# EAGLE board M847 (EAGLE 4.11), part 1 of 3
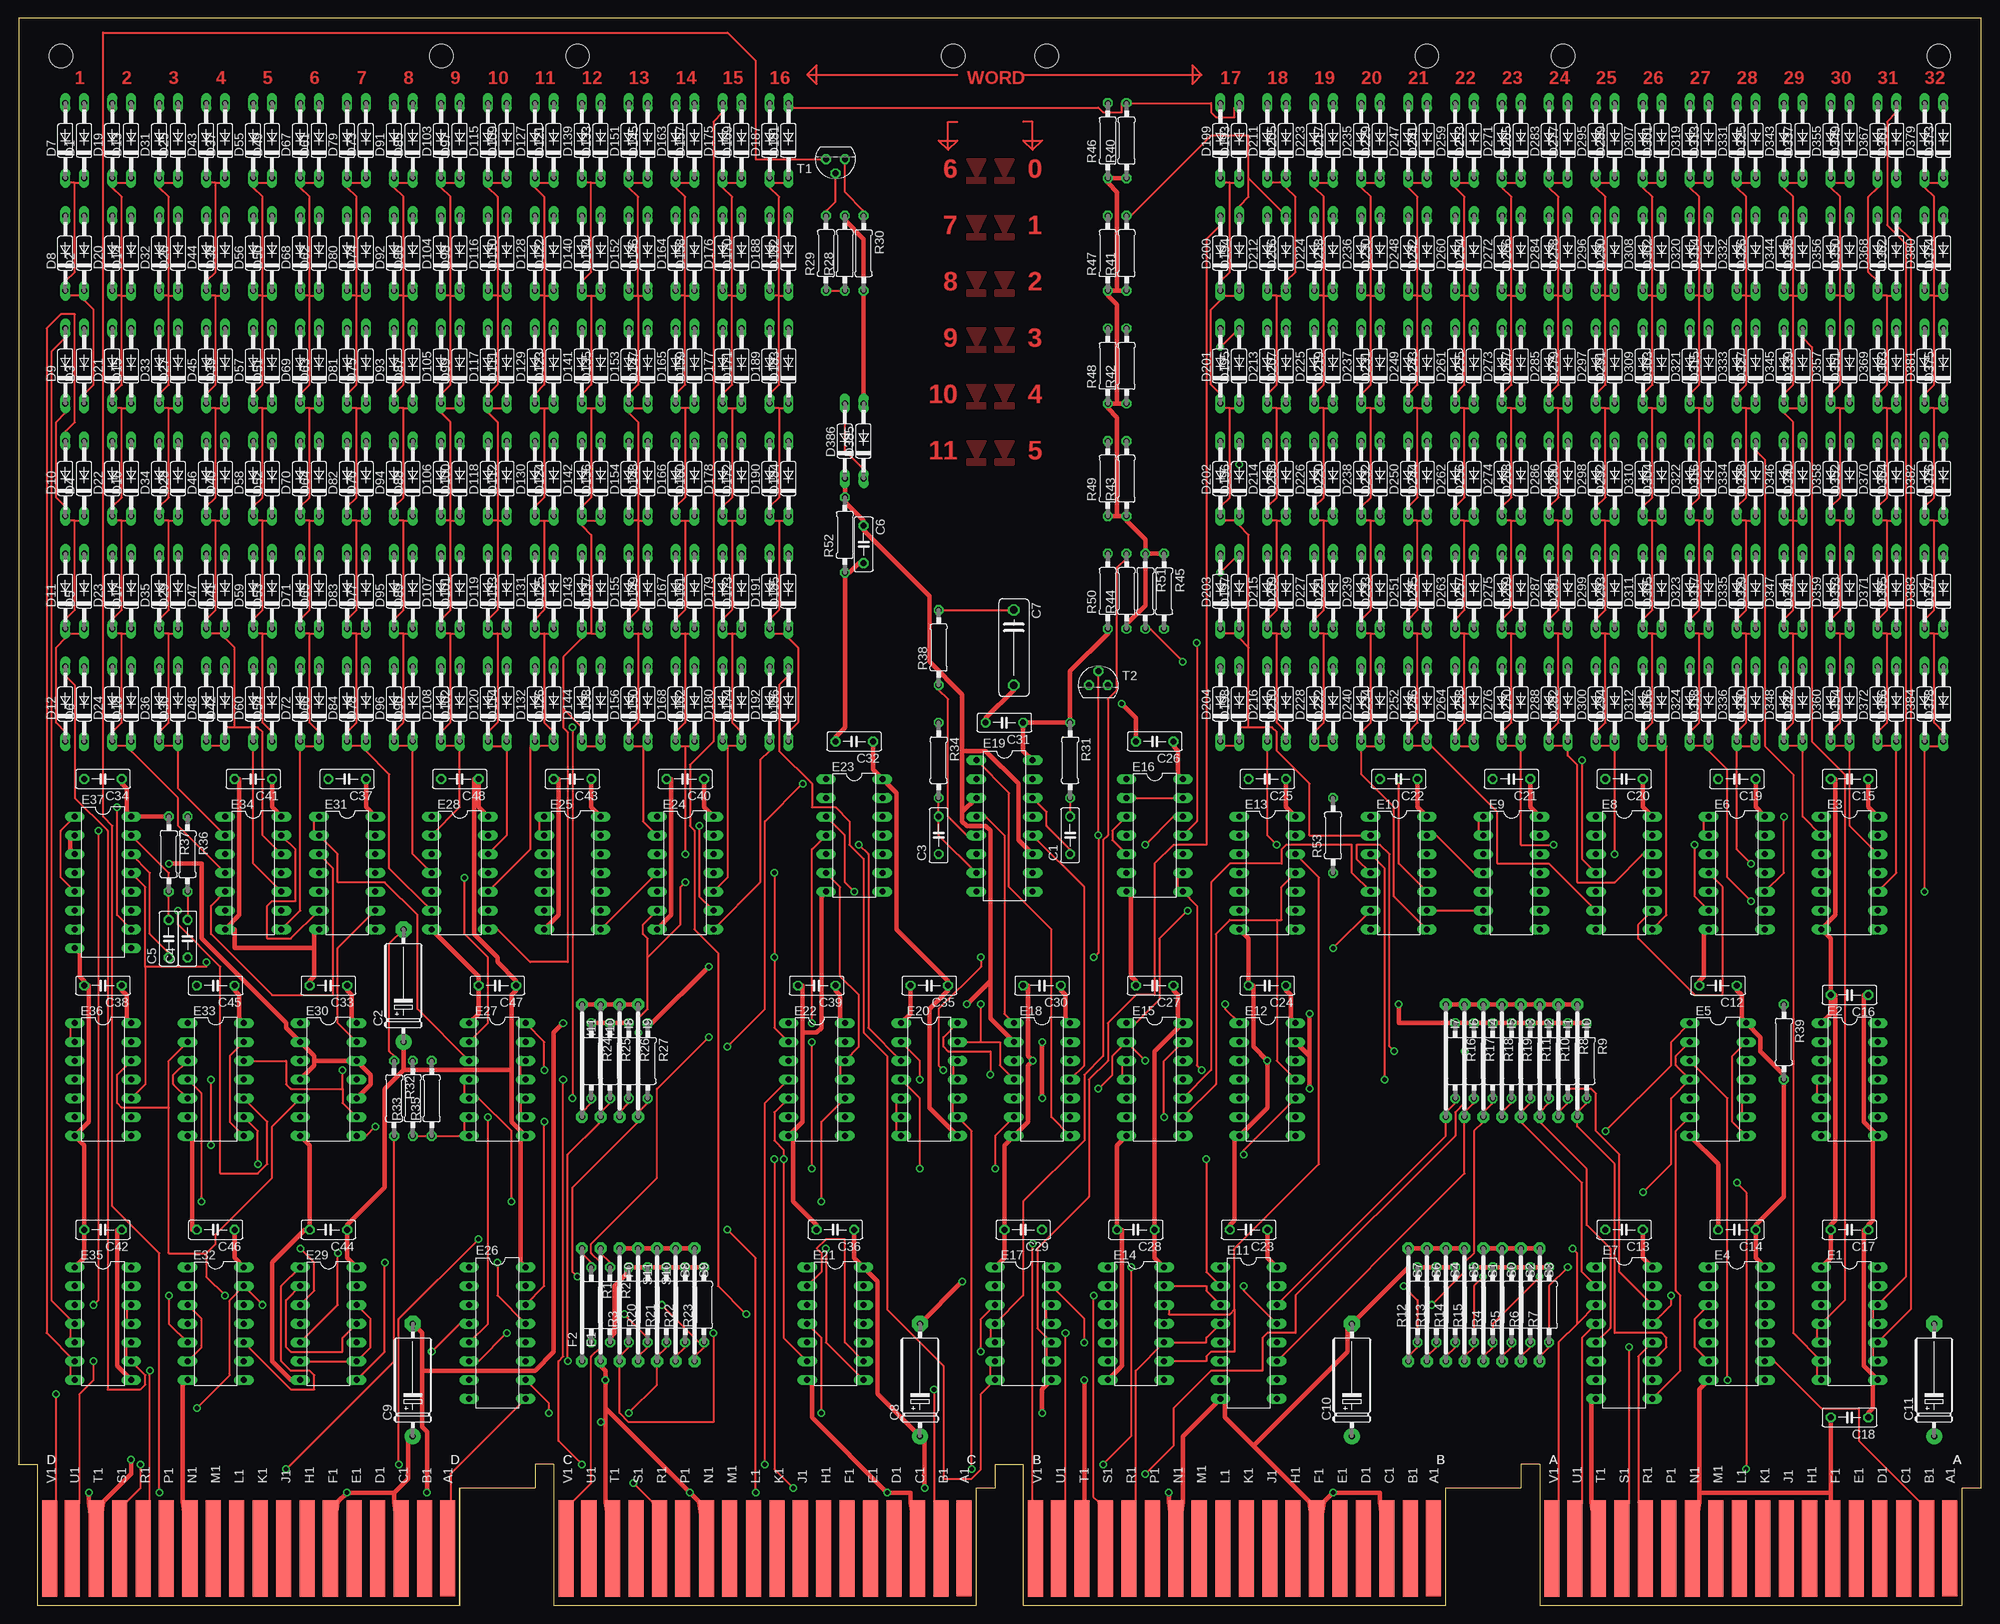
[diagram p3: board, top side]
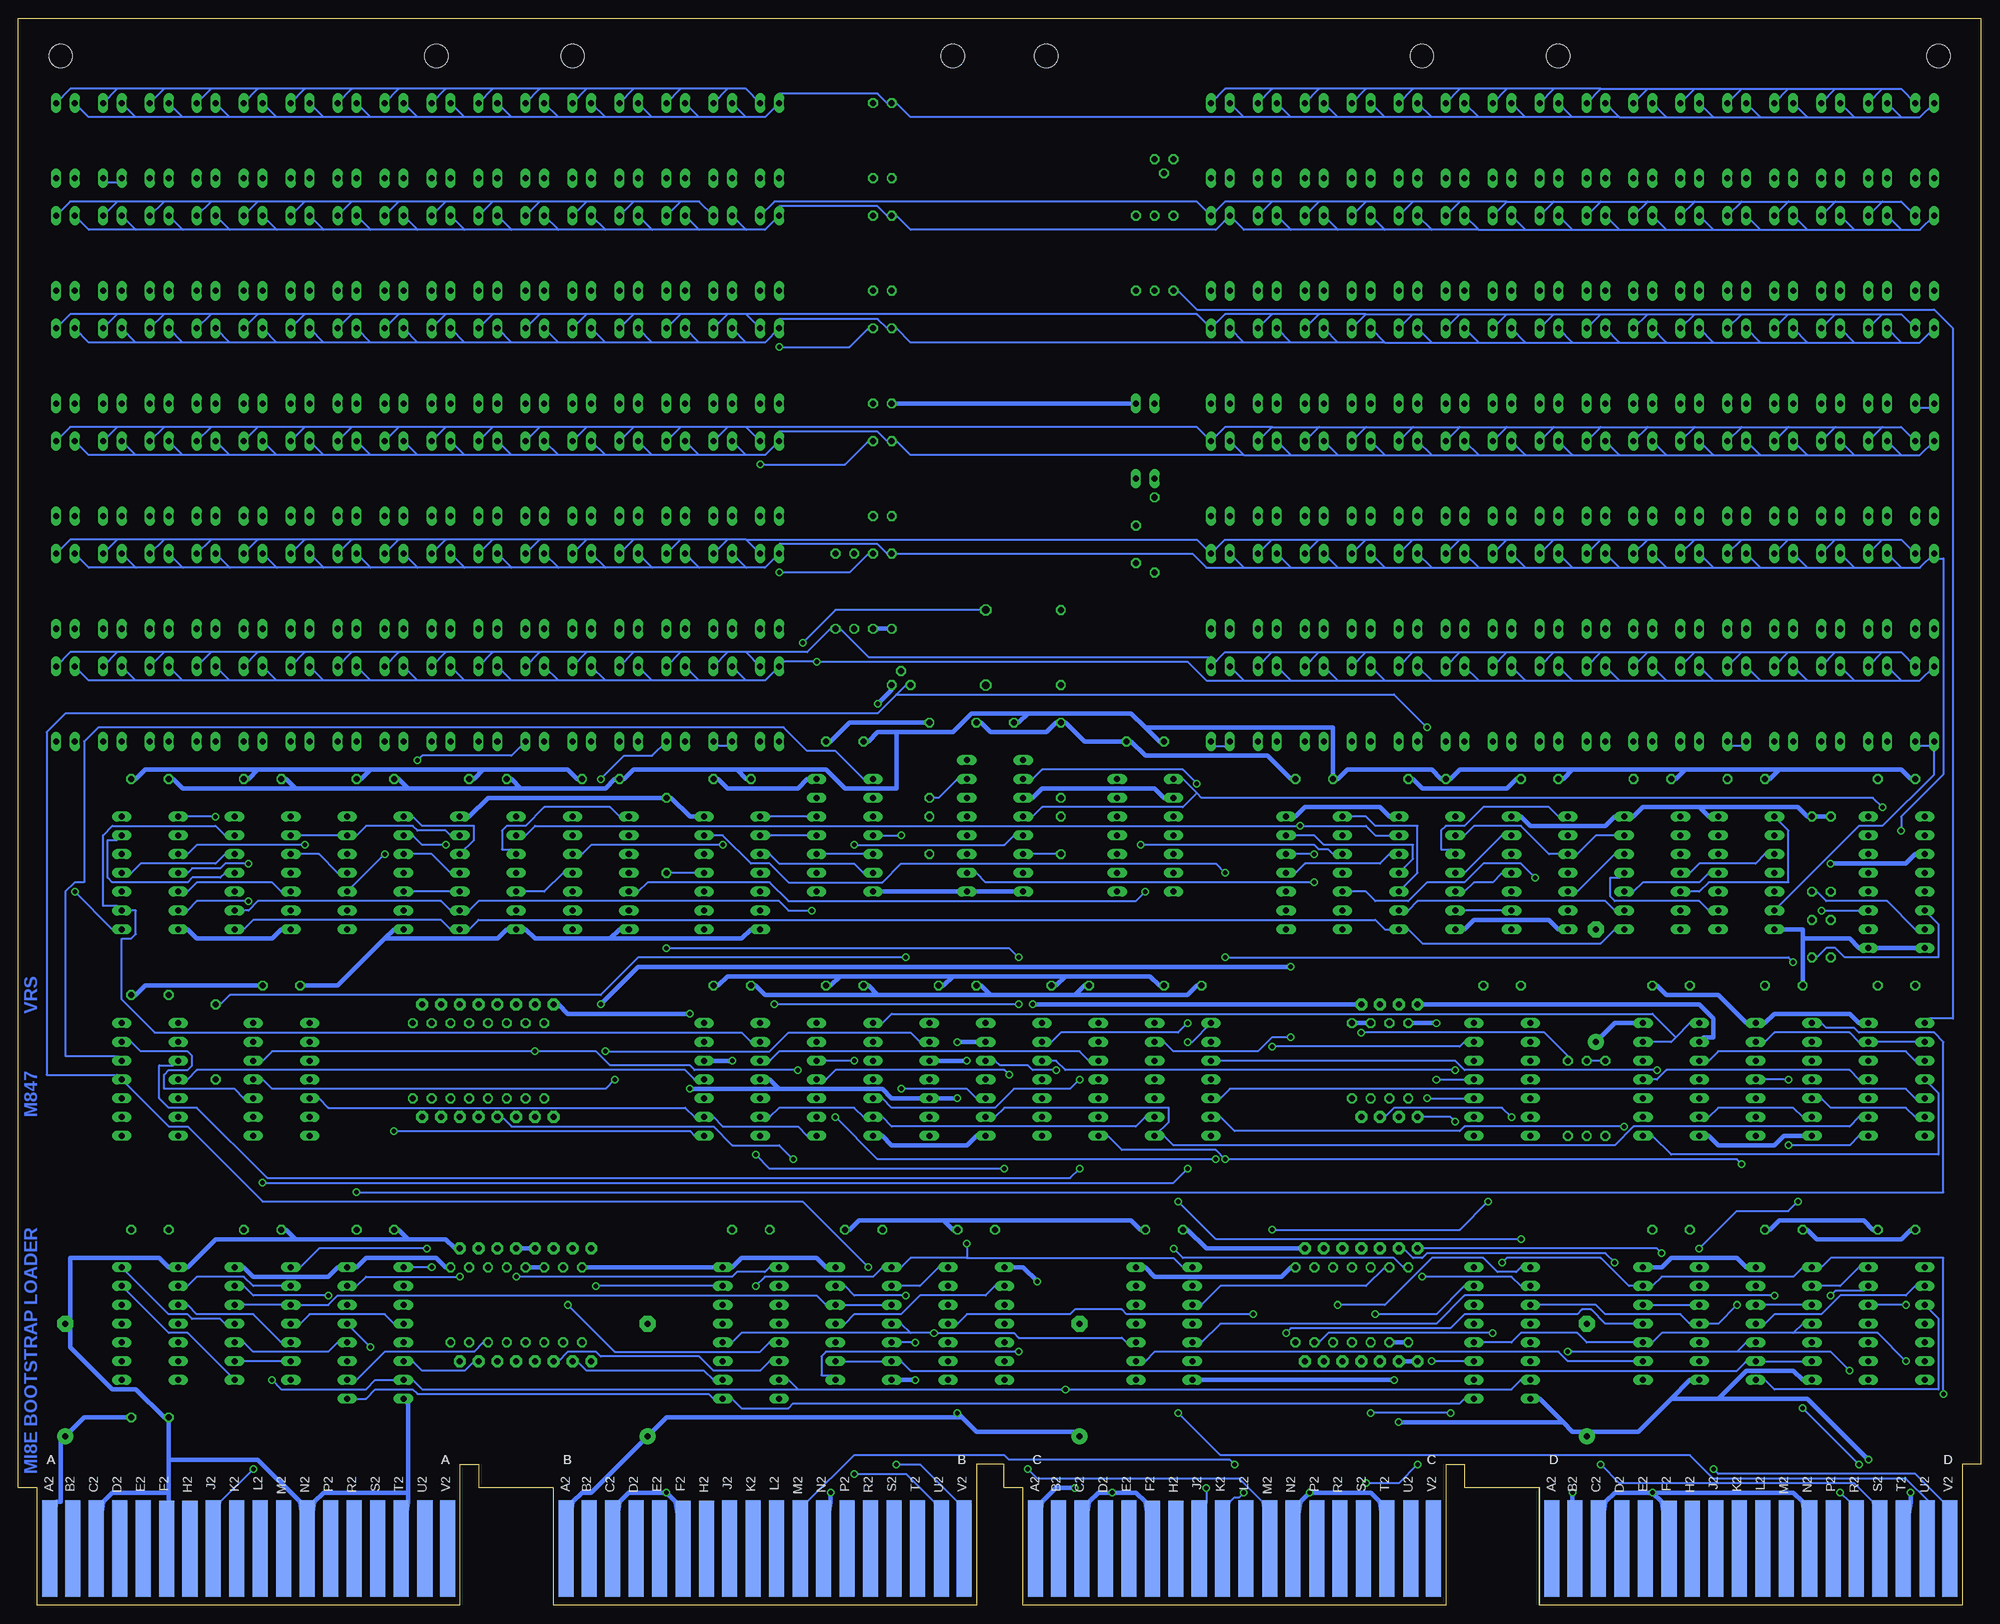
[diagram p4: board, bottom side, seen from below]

Size 265.43 x 214.63 mm. Coordinates in mm from the lower left corner, seen from the top.
Copper layers (1*16): Top 0.035mm / dielectric 1.5mm / Bottom 0.035mm
Design rules "10mils": minimum track width 10mil, minimum drill 24mil, track to track 10mil, track to pad 10mil, pad to pad 10mil, via to via 10mil, smd to smd 10mil, copper to edge 25mil, drill to drill 10mil, minimum pad ring 10mil, minimum via ring 8mil, stop-mask expansion 0mil, vias tented up to drill 0mil, thermal gap 10mil
Net classes: 1 supply: width 0.635 mm

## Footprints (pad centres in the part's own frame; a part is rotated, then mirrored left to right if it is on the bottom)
C050-025X075 = drill 0.813 octagon: 1 -2.54,0; 2 2.54,0
E15-5 = drill 0.813 pad 2.159 round: + -7.62,0 | drill 0.813 pad 2.159 octagon: - 7.62,0
C102-043X133 = drill 1.016 octagon: 1 -5.08,0; 2 5.08,0
DO35-10 = drill 0.813 long: A 5.08,0; C -5.08,0
DIL14 = drill 0.813 long: 1 -7.62,-3.81; 2 -5.08,-3.81; 3 -2.54,-3.81; 4 0,-3.81; 5 2.54,-3.81; 6 5.08,-3.81; 7 7.62,-3.81; 8 7.62,3.81; 9 5.08,3.81; 10 2.54,3.81; 11 0,3.81; 12 -2.54,3.81; 13 -5.08,3.81; 14 -7.62,3.81
DIL16 = drill 0.813 long: 1 -8.89,-3.81; 2 -6.35,-3.81; 3 -3.81,-3.81; 4 -1.27,-3.81; 5 1.27,-3.81; 6 3.81,-3.81; 7 6.35,-3.81; 8 8.89,-3.81; 9 8.89,3.81; 10 6.35,3.81; 11 3.81,3.81; 12 1.27,3.81; 13 -1.27,3.81; 14 -3.81,3.81; 15 -6.35,3.81; 16 -8.89,3.81
15 = drill 0.813 pad 1.6 octagon: 1 -7.62,0; 2 7.62,0
0207/10 = drill 0.813 octagon: 1 -5.08,0; 2 5.08,0
TO92 = drill 0.813 octagon: 1 1.27,0; 2 0,1.905; 3 -1.27,0
OMNIBUS = hole 3.175: 208.915,209.55; 259.715,209.55; 190.5,209.55; 139.065,209.55; 75.616,209.55; 126.416,209.55; 57.201,209.55; 5.766,209.55
EDGE-CON8 = smd 2.032 x 13.017: AA1 261.223,7.709; AB1 258.118,7.684; AC1 254.956,7.684; AD1 251.765,7.684; AE1 248.59,7.693; AF1 245.389,7.668; AH1 242.24,7.668; AJ1 239.09,7.668; AK1 235.915,7.668; AL1 232.74,7.693; AM1 229.54,7.693; AN1 226.39,7.693; AP1 223.19,7.668; AR1 220.04,7.668; AS1 216.865,7.693; AT1 213.69,7.693; AU1 210.49,7.693; AV1 207.404,7.668; BA1 191.373,7.709; BB1 188.268,7.684; BC1 185.106,7.684; BD1 181.915,7.684; BE1 178.74,7.693; BF1 175.539,7.668; BH1 172.39,7.668; BJ1 169.24,7.668; BK1 166.065,7.668; BL1 162.89,7.693; BM1 159.69,7.693; BN1 156.54,7.693; BP1 153.34,7.668; BR1 150.19,7.668; BS1 147.015,7.693; BT1 143.84,7.693; BU1 140.64,7.693; BV1 137.554,7.668; CA1 127.873,7.709; CB1 124.768,7.684; CC1 121.606,7.684; CD1 118.415,7.684; CE1 115.24,7.693; CF1 112.039,7.668; CH1 108.89,7.668; CJ1 105.74,7.668; CK1 102.565,7.668; CL1 99.39,7.693; CM1 96.19,7.693; CN1 93.04,7.693; CP1 89.84,7.668; CR1 86.69,7.668; CS1 83.515,7.693; CT1 80.34,7.693; CU1 77.14,7.693; CV1 74.054,7.668; DA1 58.023,7.709; DB1 54.918,7.684; DC1 51.756,7.684; DD1 48.565,7.684; DE1 45.39,7.693; DF1 42.189,7.668; DH1 39.04,7.668; DJ1 35.89,7.668; DK1 32.715,7.668; DL1 29.54,7.693; DM1 26.34,7.693; DN1 23.19,7.693; DP1 19.99,7.668; DR1 16.84,7.668; DS1 13.665,7.693; DT1 10.49,7.693; DU1 7.29,7.693; DV1 4.204,7.668 | smd 2.032 x 13.017 bottom: AA2 261.223,7.69; AB2 258.102,7.668; AC2 254.94,7.668; AD2 251.765,7.693; AE2 248.59,7.693; AF2 245.389,7.642; AH2 242.24,7.642; AJ2 239.09,7.668; AK2 235.915,7.668; AL2 232.74,7.693; AM2 229.54,7.693; AN2 226.39,7.693; AP2 223.19,7.668; AR2 220.04,7.668; AS2 216.865,7.693; AT2 213.69,7.693; AU2 210.464,7.693; AV2 207.404,7.668; BA2 191.373,7.69; BB2 188.252,7.668; BC2 185.09,7.668; BD2 181.915,7.693; BE2 178.74,7.693; BF2 175.539,7.642; BH2 172.39,7.642; BJ2 169.24,7.668; BK2 166.065,7.668; BL2 162.89,7.693; BM2 159.69,7.693; BN2 156.54,7.693; BP2 153.34,7.668; BR2 150.19,7.668; BS2 147.015,7.693; BT2 143.84,7.693; BU2 140.614,7.693; BV2 137.554,7.668; CA2 127.873,7.69; CB2 124.752,7.668; CC2 121.59,7.668; CD2 118.415,7.693; CE2 115.24,7.693; CF2 112.039,7.642; CH2 108.89,7.642; CJ2 105.74,7.668; CK2 102.565,7.668; CL2 99.39,7.693; CM2 96.19,7.693; CN2 93.04,7.693; CP2 89.84,7.668; CR2 86.69,7.668; CS2 83.515,7.693; CT2 80.34,7.693; CU2 77.114,7.693; CV2 74.054,7.668; DA2 58.023,7.69; DB2 54.902,7.668; DC2 51.74,7.668; DD2 48.565,7.693; DE2 45.39,7.693; DF2 42.189,7.642; DH2 39.04,7.642; DJ2 35.89,7.668; DK2 32.715,7.668; DL2 29.54,7.693; DM2 26.34,7.693; DN2 23.19,7.693; DP2 19.99,7.668; DR2 16.84,7.668; DS2 13.665,7.693; DT2 10.49,7.693; DU2 7.264,7.693; DV2 4.204,7.668

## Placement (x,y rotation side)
C1  27pf  [C050-025X075]  142.24,104.14 90 top
C2  39uf  [E15-5]  52.07,83.82 90 top
C3  150pf  [C050-025X075]  124.46,104.14 90 top
C4  68pf  [C050-025X075]  22.86,90.17 90 top
C5  27pf  [C050-025X075]  20.32,90.17 90 top
C6  27pf  [C050-025X075]  114.3,143.51 270 top
C7  2700pf  [C102-043X133]  134.62,129.54 270 top
C8  6.8uf  [E15-5]  121.92,30.48 90 top
C9  6.8uf  [E15-5]  53.34,30.48 90 top
C10  6.8uf  [E15-5]  180.34,30.48 90 top
C11  6.8uf  [E15-5]  259.08,30.48 90 top
C12  .01uf  [C050-025X075]  229.87,83.82 180 top
C13  .01uf  [C050-025X075]  217.17,50.8 180 top
C14  .01uf  [C050-025X075]  232.41,50.8 180 top
C15  .01uf  [C050-025X075]  247.65,111.76 180 top
C16  .01uf  [C050-025X075]  247.65,82.55 180 top
C17  .01uf  [C050-025X075]  247.65,50.8 180 top
C18  .01uf  [C050-025X075]  247.65,25.4 180 top
C19  .01uf  [C050-025X075]  232.41,111.76 180 top
C20  .01uf  [C050-025X075]  217.17,111.76 180 top
C21  .01uf  [C050-025X075]  201.93,111.76 180 top
C22  .01uf  [C050-025X075]  186.69,111.76 180 top
C23  .01uf  [C050-025X075]  166.37,50.8 180 top
C24  .01uf  [C050-025X075]  168.91,83.82 180 top
C25  .01uf  [C050-025X075]  168.91,111.76 180 top
C26  .01uf  [C050-025X075]  153.67,116.84 180 top
C27  .01uf  [C050-025X075]  153.67,83.82 180 top
C28  .01uf  [C050-025X075]  151.13,50.8 180 top
C29  .01uf  [C050-025X075]  135.89,50.8 180 top
C30  .01uf  [C050-025X075]  138.43,83.82 180 top
C31  .01uf  [C050-025X075]  133.35,119.38 180 top
C32  .01uf  [C050-025X075]  113.03,116.84 180 top
C33  .01uf  [C050-025X075]  41.91,83.82 180 top
C34  .01uf  [C050-025X075]  11.43,111.76 180 top
C35  .01uf  [C050-025X075]  123.19,83.82 180 top
C36  .01uf  [C050-025X075]  110.49,50.8 180 top
C37  .01uf  [C050-025X075]  44.45,111.76 180 top
C38  .01uf  [C050-025X075]  11.43,83.82 180 top
C39  .01uf  [C050-025X075]  107.95,83.82 180 top
C40  .01uf  [C050-025X075]  90.17,111.76 180 top
C41  .01uf  [C050-025X075]  31.75,111.76 180 top
C42  .01uf  [C050-025X075]  11.43,50.8 180 top
C43  .01uf  [C050-025X075]  74.93,111.76 180 top
C44  .01uf  [C050-025X075]  41.91,50.8 180 top
C45  .01uf  [C050-025X075]  26.67,83.82 180 top
C46  .01uf  [C050-025X075]  26.67,50.8 180 top
C47  .01uf  [C050-025X075]  64.77,83.82 180 top
C48  .01uf  [C050-025X075]  59.69,111.76 180 top
D1  1N4148  [DO35-10]  8.89,198.12 90 top
D2  1N4148  [DO35-10]  8.89,182.88 90 top
D3  1N4148  [DO35-10]  8.89,167.64 90 top
D4  1N4148  [DO35-10]  8.89,152.4 90 top
D5  1N4148  [DO35-10]  8.89,137.16 90 top
D6  1N4148  [DO35-10]  8.89,121.92 90 top
D7  1N4148  [DO35-10]  6.35,198.12 90 top
D8  1N4148  [DO35-10]  6.35,182.88 90 top
D9  1N4148  [DO35-10]  6.35,167.64 90 top
D10  1N4148  [DO35-10]  6.35,152.4 90 top
D11  1N4148  [DO35-10]  6.35,137.16 90 top
D12  1N4148  [DO35-10]  6.35,121.92 90 top
D13  1N4148  [DO35-10]  15.24,198.12 90 top
D14  1N4148  [DO35-10]  15.24,182.88 90 top
D15  1N4148  [DO35-10]  15.24,167.64 90 top
D16  1N4148  [DO35-10]  15.24,152.4 90 top
D17  1N4148  [DO35-10]  15.24,137.16 90 top
D18  1N4148  [DO35-10]  15.24,121.92 90 top
D19  1N4148  [DO35-10]  12.7,198.12 90 top
D20  1N4148  [DO35-10]  12.7,182.88 90 top
D21  1N4148  [DO35-10]  12.7,167.64 90 top
D22  1N4148  [DO35-10]  12.7,152.4 90 top
D23  1N4148  [DO35-10]  12.7,137.16 90 top
D24  1N4148  [DO35-10]  12.7,121.92 90 top
D25  1N4148  [DO35-10]  21.59,198.12 90 top
D26  1N4148  [DO35-10]  21.59,182.88 90 top
D27  1N4148  [DO35-10]  21.59,167.64 90 top
D28  1N4148  [DO35-10]  21.59,152.4 90 top
D29  1N4148  [DO35-10]  21.59,137.16 90 top
D30  1N4148  [DO35-10]  21.59,121.92 90 top
D31  1N4148  [DO35-10]  19.05,198.12 90 top
D32  1N4148  [DO35-10]  19.05,182.88 90 top
D33  1N4148  [DO35-10]  19.05,167.64 90 top
D34  1N4148  [DO35-10]  19.05,152.4 90 top
D35  1N4148  [DO35-10]  19.05,137.16 90 top
D36  1N4148  [DO35-10]  19.05,121.92 90 top
D37  1N4148  [DO35-10]  27.94,198.12 90 top
D38  1N4148  [DO35-10]  27.94,182.88 90 top
D39  1N4148  [DO35-10]  27.94,167.64 90 top
D40  1N4148  [DO35-10]  27.94,152.4 90 top
D41  1N4148  [DO35-10]  27.94,137.16 90 top
D42  1N4148  [DO35-10]  27.94,121.92 90 top
D43  1N4148  [DO35-10]  25.4,198.12 90 top
D44  1N4148  [DO35-10]  25.4,182.88 90 top
D45  1N4148  [DO35-10]  25.4,167.64 90 top
D46  1N4148  [DO35-10]  25.4,152.4 90 top
D47  1N4148  [DO35-10]  25.4,137.16 90 top
D48  1N4148  [DO35-10]  25.4,121.92 90 top
D49  1N4148  [DO35-10]  34.29,198.12 90 top
D50  1N4148  [DO35-10]  34.29,182.88 90 top
D51  1N4148  [DO35-10]  34.29,167.64 90 top
D52  1N4148  [DO35-10]  34.29,152.4 90 top
D53  1N4148  [DO35-10]  34.29,137.16 90 top
D54  1N4148  [DO35-10]  34.29,121.92 90 top
D55  1N4148  [DO35-10]  31.75,198.12 90 top
D56  1N4148  [DO35-10]  31.75,182.88 90 top
D57  1N4148  [DO35-10]  31.75,167.64 90 top
D58  1N4148  [DO35-10]  31.75,152.4 90 top
D59  1N4148  [DO35-10]  31.75,137.16 90 top
D60  1N4148  [DO35-10]  31.75,121.92 90 top
D61  1N4148  [DO35-10]  40.64,198.12 90 top
D62  1N4148  [DO35-10]  40.64,182.88 90 top
D63  1N4148  [DO35-10]  40.64,167.64 90 top
D64  1N4148  [DO35-10]  40.64,152.4 90 top
D65  1N4148  [DO35-10]  40.64,137.16 90 top
D66  1N4148  [DO35-10]  40.64,121.92 90 top
D67  1N4148  [DO35-10]  38.1,198.12 90 top
D68  1N4148  [DO35-10]  38.1,182.88 90 top
D69  1N4148  [DO35-10]  38.1,167.64 90 top
D70  1N4148  [DO35-10]  38.1,152.4 90 top
D71  1N4148  [DO35-10]  38.1,137.16 90 top
D72  1N4148  [DO35-10]  38.1,121.92 90 top
D73  1N4148  [DO35-10]  46.99,198.12 90 top
D74  1N4148  [DO35-10]  46.99,182.88 90 top
D75  1N4148  [DO35-10]  46.99,167.64 90 top
D76  1N4148  [DO35-10]  46.99,152.4 90 top
D77  1N4148  [DO35-10]  46.99,137.16 90 top
D78  1N4148  [DO35-10]  46.99,121.92 90 top
D79  1N4148  [DO35-10]  44.45,198.12 90 top
D80  1N4148  [DO35-10]  44.45,182.88 90 top
D81  1N4148  [DO35-10]  44.45,167.64 90 top
D82  1N4148  [DO35-10]  44.45,152.4 90 top
D83  1N4148  [DO35-10]  44.45,137.16 90 top
D84  1N4148  [DO35-10]  44.45,121.92 90 top
D85  1N4148  [DO35-10]  53.34,198.12 90 top
D86  1N4148  [DO35-10]  53.34,182.88 90 top
D87  1N4148  [DO35-10]  53.34,167.64 90 top
D88  1N4148  [DO35-10]  53.34,152.4 90 top
D89  1N4148  [DO35-10]  53.34,137.16 90 top
D90  1N4148  [DO35-10]  53.34,121.92 90 top
D91  1N4148  [DO35-10]  50.8,198.12 90 top
D92  1N4148  [DO35-10]  50.8,182.88 90 top
D93  1N4148  [DO35-10]  50.8,167.64 90 top
D94  1N4148  [DO35-10]  50.8,152.4 90 top
D95  1N4148  [DO35-10]  50.8,137.16 90 top
D96  1N4148  [DO35-10]  50.8,121.92 90 top
D97  1N4148  [DO35-10]  59.69,198.12 90 top
D98  1N4148  [DO35-10]  59.69,182.88 90 top
D99  1N4148  [DO35-10]  59.69,167.64 90 top
D100  1N4148  [DO35-10]  59.69,152.4 90 top
D101  1N4148  [DO35-10]  59.69,137.16 90 top
D102  1N4148  [DO35-10]  59.69,121.92 90 top
D103  1N4148  [DO35-10]  57.15,198.12 90 top
D104  1N4148  [DO35-10]  57.15,182.88 90 top
D105  1N4148  [DO35-10]  57.15,167.64 90 top
D106  1N4148  [DO35-10]  57.15,152.4 90 top
D107  1N4148  [DO35-10]  57.15,137.16 90 top
D108  1N4148  [DO35-10]  57.15,121.92 90 top
D109  1N4148  [DO35-10]  66.04,198.12 90 top
D110  1N4148  [DO35-10]  66.04,182.88 90 top
D111  1N4148  [DO35-10]  66.04,167.64 90 top
D112  1N4148  [DO35-10]  66.04,152.4 90 top
D113  1N4148  [DO35-10]  66.04,137.16 90 top
D114  1N4148  [DO35-10]  66.04,121.92 90 top
D115  1N4148  [DO35-10]  63.5,198.12 90 top
D116  1N4148  [DO35-10]  63.5,182.88 90 top
D117  1N4148  [DO35-10]  63.5,167.64 90 top
D118  1N4148  [DO35-10]  63.5,152.4 90 top
D119  1N4148  [DO35-10]  63.5,137.16 90 top
D120  1N4148  [DO35-10]  63.5,121.92 90 top
D121  1N4148  [DO35-10]  72.39,198.12 90 top
D122  1N4148  [DO35-10]  72.39,182.88 90 top
D123  1N4148  [DO35-10]  72.39,167.64 90 top
D124  1N4148  [DO35-10]  72.39,152.4 90 top
D125  1N4148  [DO35-10]  72.39,137.16 90 top
D126  1N4148  [DO35-10]  72.39,121.92 90 top
D127  1N4148  [DO35-10]  69.85,198.12 90 top
D128  1N4148  [DO35-10]  69.85,182.88 90 top
D129  1N4148  [DO35-10]  69.85,167.64 90 top
D130  1N4148  [DO35-10]  69.85,152.4 90 top
D131  1N4148  [DO35-10]  69.85,137.16 90 top
D132  1N4148  [DO35-10]  69.85,121.92 90 top
D133  1N4148  [DO35-10]  78.74,198.12 90 top
D134  1N4148  [DO35-10]  78.74,182.88 90 top
D135  1N4148  [DO35-10]  78.74,167.64 90 top
D136  1N4148  [DO35-10]  78.74,152.4 90 top
D137  1N4148  [DO35-10]  78.74,137.16 90 top
D138  1N4148  [DO35-10]  78.74,121.92 90 top
D139  1N4148  [DO35-10]  76.2,198.12 90 top
D140  1N4148  [DO35-10]  76.2,182.88 90 top
D141  1N4148  [DO35-10]  76.2,167.64 90 top
D142  1N4148  [DO35-10]  76.2,152.4 90 top
D143  1N4148  [DO35-10]  76.2,137.16 90 top
D144  1N4148  [DO35-10]  76.2,121.92 90 top
D145  1N4148  [DO35-10]  85.09,198.12 90 top
D146  1N4148  [DO35-10]  85.09,182.88 90 top
D147  1N4148  [DO35-10]  85.09,167.64 90 top
D148  1N4148  [DO35-10]  85.09,152.4 90 top
D149  1N4148  [DO35-10]  85.09,137.16 90 top
D150  1N4148  [DO35-10]  85.09,121.92 90 top
D151  1N4148  [DO35-10]  82.55,198.12 90 top
D152  1N4148  [DO35-10]  82.55,182.88 90 top
D153  1N4148  [DO35-10]  82.55,167.64 90 top
D154  1N4148  [DO35-10]  82.55,152.4 90 top
D155  1N4148  [DO35-10]  82.55,137.16 90 top
D156  1N4148  [DO35-10]  82.55,121.92 90 top
D157  1N4148  [DO35-10]  91.44,198.12 90 top
D158  1N4148  [DO35-10]  91.44,182.88 90 top
D159  1N4148  [DO35-10]  91.44,167.64 90 top
D160  1N4148  [DO35-10]  91.44,152.4 90 top
D161  1N4148  [DO35-10]  91.44,137.16 90 top
D162  1N4148  [DO35-10]  91.44,121.92 90 top
D163  1N4148  [DO35-10]  88.9,198.12 90 top
D164  1N4148  [DO35-10]  88.9,182.88 90 top
D165  1N4148  [DO35-10]  88.9,167.64 90 top
D166  1N4148  [DO35-10]  88.9,152.4 90 top
D167  1N4148  [DO35-10]  88.9,137.16 90 top
D168  1N4148  [DO35-10]  88.9,121.92 90 top
D169  1N4148  [DO35-10]  97.79,198.12 90 top
D170  1N4148  [DO35-10]  97.79,182.88 90 top
D171  1N4148  [DO35-10]  97.79,167.64 90 top
D172  1N4148  [DO35-10]  97.79,152.4 90 top
D173  1N4148  [DO35-10]  97.79,137.16 90 top
D174  1N4148  [DO35-10]  97.79,121.92 90 top
D175  1N4148  [DO35-10]  95.25,198.12 90 top
D176  1N4148  [DO35-10]  95.25,182.88 90 top
D177  1N4148  [DO35-10]  95.25,167.64 90 top
D178  1N4148  [DO35-10]  95.25,152.4 90 top
D179  1N4148  [DO35-10]  95.25,137.16 90 top
D180  1N4148  [DO35-10]  95.25,121.92 90 top
D181  1N4148  [DO35-10]  104.14,198.12 90 top
D182  1N4148  [DO35-10]  104.14,182.88 90 top
D183  1N4148  [DO35-10]  104.14,167.64 90 top
D184  1N4148  [DO35-10]  104.14,152.4 90 top
D185  1N4148  [DO35-10]  104.14,137.16 90 top
D186  1N4148  [DO35-10]  104.14,121.92 90 top
D187  1N4148  [DO35-10]  101.6,198.12 90 top
D188  1N4148  [DO35-10]  101.6,182.88 90 top
D189  1N4148  [DO35-10]  101.6,167.64 90 top
D190  1N4148  [DO35-10]  101.6,152.4 90 top
D191  1N4148  [DO35-10]  101.6,137.16 90 top
D192  1N4148  [DO35-10]  101.6,121.92 90 top
D193  1N4148  [DO35-10]  165.1,198.12 90 top
D194  1N4148  [DO35-10]  165.1,182.88 90 top
D195  1N4148  [DO35-10]  165.1,167.64 90 top
D196  1N4148  [DO35-10]  165.1,152.4 90 top
D197  1N4148  [DO35-10]  165.1,137.16 90 top
D198  1N4148  [DO35-10]  165.1,121.92 90 top
D199  1N4148  [DO35-10]  162.56,198.12 90 top
D200  1N4148  [DO35-10]  162.56,182.88 90 top
D201  1N4148  [DO35-10]  162.56,167.64 90 top
D202  1N4148  [DO35-10]  162.56,152.4 90 top
D203  1N4148  [DO35-10]  162.56,137.16 90 top
D204  1N4148  [DO35-10]  162.56,121.92 90 top
D205  1N4148  [DO35-10]  171.45,198.12 90 top
D206  1N4148  [DO35-10]  171.45,182.88 90 top
D207  1N4148  [DO35-10]  171.45,167.64 90 top
D208  1N4148  [DO35-10]  171.45,152.4 90 top
D209  1N4148  [DO35-10]  171.45,137.16 90 top
D210  1N4148  [DO35-10]  171.45,121.92 90 top
D211  1N4148  [DO35-10]  168.91,198.12 90 top
D212  1N4148  [DO35-10]  168.91,182.88 90 top
D213  1N4148  [DO35-10]  168.91,167.64 90 top
D214  1N4148  [DO35-10]  168.91,152.4 90 top
D215  1N4148  [DO35-10]  168.91,137.16 90 top
D216  1N4148  [DO35-10]  168.91,121.92 90 top
D217  1N4148  [DO35-10]  177.8,198.12 90 top
D218  1N4148  [DO35-10]  177.8,182.88 90 top
D219  1N4148  [DO35-10]  177.8,167.64 90 top
D220  1N4148  [DO35-10]  177.8,152.4 90 top
D221  1N4148  [DO35-10]  177.8,137.16 90 top
D222  1N4148  [DO35-10]  177.8,121.92 90 top
D223  1N4148  [DO35-10]  175.26,198.12 90 top
D224  1N4148  [DO35-10]  175.26,182.88 90 top
D225  1N4148  [DO35-10]  175.26,167.64 90 top
D226  1N4148  [DO35-10]  175.26,152.4 90 top
D227  1N4148  [DO35-10]  175.26,137.16 90 top
D228  1N4148  [DO35-10]  175.26,121.92 90 top
D229  1N4148  [DO35-10]  184.15,198.12 90 top
D230  1N4148  [DO35-10]  184.15,182.88 90 top
D231  1N4148  [DO35-10]  184.15,167.64 90 top
D232  1N4148  [DO35-10]  184.15,152.4 90 top
D233  1N4148  [DO35-10]  184.15,137.16 90 top
D234  1N4148  [DO35-10]  184.15,121.92 90 top
D235  1N4148  [DO35-10]  181.61,198.12 90 top
D236  1N4148  [DO35-10]  181.61,182.88 90 top
D237  1N4148  [DO35-10]  181.61,167.64 90 top
D238  1N4148  [DO35-10]  181.61,152.4 90 top
D239  1N4148  [DO35-10]  181.61,137.16 90 top
D240  1N4148  [DO35-10]  181.61,121.92 90 top
D241  1N4148  [DO35-10]  190.5,198.12 90 top
D242  1N4148  [DO35-10]  190.5,182.88 90 top
D243  1N4148  [DO35-10]  190.5,167.64 90 top
D244  1N4148  [DO35-10]  190.5,152.4 90 top
D245  1N4148  [DO35-10]  190.5,137.16 90 top
D246  1N4148  [DO35-10]  190.5,121.92 90 top
D247  1N4148  [DO35-10]  187.96,198.12 90 top
D248  1N4148  [DO35-10]  187.96,182.88 90 top
D249  1N4148  [DO35-10]  187.96,167.64 90 top
D250  1N4148  [DO35-10]  187.96,152.4 90 top
D251  1N4148  [DO35-10]  187.96,137.16 90 top
D252  1N4148  [DO35-10]  187.96,121.92 90 top
D253  1N4148  [DO35-10]  196.85,198.12 90 top
D254  1N4148  [DO35-10]  196.85,182.88 90 top
D255  1N4148  [DO35-10]  196.85,167.64 90 top
D256  1N4148  [DO35-10]  196.85,152.4 90 top
D257  1N4148  [DO35-10]  196.85,137.16 90 top
D258  1N4148  [DO35-10]  196.85,121.92 90 top
D259  1N4148  [DO35-10]  194.31,198.12 90 top
D260  1N4148  [DO35-10]  194.31,182.88 90 top
D261  1N4148  [DO35-10]  194.31,167.64 90 top
D262  1N4148  [DO35-10]  194.31,152.4 90 top
D263  1N4148  [DO35-10]  194.31,137.16 90 top
D264  1N4148  [DO35-10]  194.31,121.92 90 top
D265  1N4148  [DO35-10]  203.2,198.12 90 top
D266  1N4148  [DO35-10]  203.2,182.88 90 top
D267  1N4148  [DO35-10]  203.2,167.64 90 top
D268  1N4148  [DO35-10]  203.2,152.4 90 top
D269  1N4148  [DO35-10]  203.2,137.16 90 top
D270  1N4148  [DO35-10]  203.2,121.92 90 top
D271  1N4148  [DO35-10]  200.66,198.12 90 top
D272  1N4148  [DO35-10]  200.66,182.88 90 top
D273  1N4148  [DO35-10]  200.66,167.64 90 top
D274  1N4148  [DO35-10]  200.66,152.4 90 top
D275  1N4148  [DO35-10]  200.66,137.16 90 top
D276  1N4148  [DO35-10]  200.66,121.92 90 top
D277  1N4148  [DO35-10]  209.55,198.12 90 top
D278  1N4148  [DO35-10]  209.55,182.88 90 top
D279  1N4148  [DO35-10]  209.55,167.64 90 top
D280  1N4148  [DO35-10]  209.55,152.4 90 top
D281  1N4148  [DO35-10]  209.55,137.16 90 top
D282  1N4148  [DO35-10]  209.55,121.92 90 top
D283  1N4148  [DO35-10]  207.01,198.12 90 top
D284  1N4148  [DO35-10]  207.01,182.88 90 top
D285  1N4148  [DO35-10]  207.01,167.64 90 top
D286  1N4148  [DO35-10]  207.01,152.4 90 top
D287  1N4148  [DO35-10]  207.01,137.16 90 top
D288  1N4148  [DO35-10]  207.01,121.92 90 top
D289  1N4148  [DO35-10]  215.9,198.12 90 top
D290  1N4148  [DO35-10]  215.9,182.88 90 top
D291  1N4148  [DO35-10]  215.9,167.64 90 top
D292  1N4148  [DO35-10]  215.9,152.4 90 top
D293  1N4148  [DO35-10]  215.9,137.16 90 top
D294  1N4148  [DO35-10]  215.9,121.92 90 top
D295  1N4148  [DO35-10]  213.36,198.12 90 top
D296  1N4148  [DO35-10]  213.36,182.88 90 top
D297  1N4148  [DO35-10]  213.36,167.64 90 top
D298  1N4148  [DO35-10]  213.36,152.4 90 top
D299  1N4148  [DO35-10]  213.36,137.16 90 top
D300  1N4148  [DO35-10]  213.36,121.92 90 top
D301  1N4148  [DO35-10]  222.25,198.12 90 top
D302  1N4148  [DO35-10]  222.25,182.88 90 top
D303  1N4148  [DO35-10]  222.25,167.64 90 top
D304  1N4148  [DO35-10]  222.25,152.4 90 top
D305  1N4148  [DO35-10]  222.25,137.16 90 top
D306  1N4148  [DO35-10]  222.25,121.92 90 top
D307  1N4148  [DO35-10]  219.71,198.12 90 top
D308  1N4148  [DO35-10]  219.71,182.88 90 top
D309  1N4148  [DO35-10]  219.71,167.64 90 top
D310  1N4148  [DO35-10]  219.71,152.4 90 top
D311  1N4148  [DO35-10]  219.71,137.16 90 top
D312  1N4148  [DO35-10]  219.71,121.92 90 top
D313  1N4148  [DO35-10]  228.6,198.12 90 top
D314  1N4148  [DO35-10]  228.6,182.88 90 top
D315  1N4148  [DO35-10]  228.6,167.64 90 top
D316  1N4148  [DO35-10]  228.6,152.4 90 top
D317  1N4148  [DO35-10]  228.6,137.16 90 top
D318  1N4148  [DO35-10]  228.6,121.92 90 top
D319  1N4148  [DO35-10]  226.06,198.12 90 top
D320  1N4148  [DO35-10]  226.06,182.88 90 top
D321  1N4148  [DO35-10]  226.06,167.64 90 top
D322  1N4148  [DO35-10]  226.06,152.4 90 top
D323  1N4148  [DO35-10]  226.06,137.16 90 top
D324  1N4148  [DO35-10]  226.06,121.92 90 top
D325  1N4148  [DO35-10]  234.95,198.12 90 top
D326  1N4148  [DO35-10]  234.95,182.88 90 top
D327  1N4148  [DO35-10]  234.95,167.64 90 top
D328  1N4148  [DO35-10]  234.95,152.4 90 top
D329  1N4148  [DO35-10]  234.95,137.16 90 top
D330  1N4148  [DO35-10]  234.95,121.92 90 top
D331  1N4148  [DO35-10]  232.41,198.12 90 top
D332  1N4148  [DO35-10]  232.41,182.88 90 top
D333  1N4148  [DO35-10]  232.41,167.64 90 top
D334  1N4148  [DO35-10]  232.41,152.4 90 top
D335  1N4148  [DO35-10]  232.41,137.16 90 top
D336  1N4148  [DO35-10]  232.41,121.92 90 top
D337  1N4148  [DO35-10]  241.3,198.12 90 top
D338  1N4148  [DO35-10]  241.3,182.88 90 top
D339  1N4148  [DO35-10]  241.3,167.64 90 top
D340  1N4148  [DO35-10]  241.3,152.4 90 top
D341  1N4148  [DO35-10]  241.3,137.16 90 top
D342  1N4148  [DO35-10]  241.3,121.92 90 top
D343  1N4148  [DO35-10]  238.76,198.12 90 top
D344  1N4148  [DO35-10]  238.76,182.88 90 top
D345  1N4148  [DO35-10]  238.76,167.64 90 top
D346  1N4148  [DO35-10]  238.76,152.4 90 top
D347  1N4148  [DO35-10]  238.76,137.16 90 top
D348  1N4148  [DO35-10]  238.76,121.92 90 top
D349  1N4148  [DO35-10]  247.65,198.12 90 top
D350  1N4148  [DO35-10]  247.65,182.88 90 top
D351  1N4148  [DO35-10]  247.65,167.64 90 top
D352  1N4148  [DO35-10]  247.65,152.4 90 top
D353  1N4148  [DO35-10]  247.65,137.16 90 top
D354  1N4148  [DO35-10]  247.65,121.92 90 top
D355  1N4148  [DO35-10]  245.11,198.12 90 top
D356  1N4148  [DO35-10]  245.11,182.88 90 top
D357  1N4148  [DO35-10]  245.11,167.64 90 top
D358  1N4148  [DO35-10]  245.11,152.4 90 top
D359  1N4148  [DO35-10]  245.11,137.16 90 top
D360  1N4148  [DO35-10]  245.11,121.92 90 top
D361  1N4148  [DO35-10]  254,198.12 90 top
D362  1N4148  [DO35-10]  254,182.88 90 top
D363  1N4148  [DO35-10]  254,167.64 90 top
D364  1N4148  [DO35-10]  254,152.4 90 top
D365  1N4148  [DO35-10]  254,137.16 90 top
D366  1N4148  [DO35-10]  254,121.92 90 top
D367  1N4148  [DO35-10]  251.46,198.12 90 top
D368  1N4148  [DO35-10]  251.46,182.88 90 top
D369  1N4148  [DO35-10]  251.46,167.64 90 top
D370  1N4148  [DO35-10]  251.46,152.4 90 top
D371  1N4148  [DO35-10]  251.46,137.16 90 top
D372  1N4148  [DO35-10]  251.46,121.92 90 top
D373  1N4148  [DO35-10]  260.35,198.12 90 top
D374  1N4148  [DO35-10]  260.35,182.88 90 top
D375  1N4148  [DO35-10]  260.35,167.64 90 top
D376  1N4148  [DO35-10]  260.35,152.4 90 top
D377  1N4148  [DO35-10]  260.35,137.16 90 top
D378  1N4148  [DO35-10]  260.35,121.92 90 top
D379  1N4148  [DO35-10]  257.81,198.12 90 top
D380  1N4148  [DO35-10]  257.81,182.88 90 top
D381  1N4148  [DO35-10]  257.81,167.64 90 top
D382  1N4148  [DO35-10]  257.81,152.4 90 top
D383  1N4148  [DO35-10]  257.81,137.16 90 top
D384  1N4148  [DO35-10]  257.81,121.92 90 top
D385  D662  [DO35-10]  114.3,157.48 90 top
D386  D662  [DO35-10]  111.76,157.48 90 top
E1  SP384N  [DIL14]  247.65,38.1 270 top
E2  SP380N  [DIL14]  247.65,71.12 270 top
E3  7404N  [DIL14]  247.65,99.06 270 top
E4  DS8881N  [DIL14]  232.41,38.1 270 top
E5  7400N  [DIL14]  229.87,71.12 270 top
E6  74164N  [DIL14]  232.41,99.06 270 top
E7  DEC8235  [DIL16]  217.17,36.83 270 top
E8  7404N  [DIL14]  217.17,99.06 270 top
E9  74164N  [DIL14]  201.93,99.06 270 top
E10  7404N  [DIL14]  186.69,99.06 270 top
E11  DEC8235  [DIL16]  166.37,36.83 270 top
E12  74S74N  [DIL14]  168.91,71.12 270 top
E13  7400N  [DIL14]  168.91,99.06 270 top
E14  DS8881N  [DIL14]  151.13,38.1 270 top
E15  7402N  [DIL14]  153.67,71.12 270 top
E16  7402N  [DIL14]  153.67,104.14 270 top
E17  SP384N  [DIL14]  135.89,38.1 270 top
E18  74S74N  [DIL14]  138.43,71.12 270 top
E19  74123N  [DIL16]  133.35,105.41 270 top
E20  SP380N  [DIL14]  123.19,71.12 270 top
E21  DS8881N  [DIL14]  110.49,38.1 270 top
E22  DS8881N  [DIL14]  107.95,71.12 270 top
E23  74S74N  [DIL14]  113.03,104.14 270 top
E24  7404N  [DIL14]  90.17,99.06 270 top
E25  74164N  [DIL14]  74.93,99.06 270 top
E26  DEC8235  [DIL16]  64.77,36.83 270 top
E27  SP380N  [DIL14]  64.77,71.12 270 top
E28  7404N  [DIL14]  59.69,99.06 270 top
E29  DS8881N  [DIL14]  41.91,38.1 270 top
E30  74S74N  [DIL14]  41.91,71.12 270 top
E31  74164N  [DIL14]  44.45,99.06 270 top
E32  DS8881N  [DIL14]  26.67,38.1 270 top
E33  7402N  [DIL14]  26.67,71.12 270 top
E34  7404N  [DIL14]  31.75,99.06 270 top
E35  SP384N  [DIL14]  11.43,38.1 270 top
E36  7400N  [DIL14]  11.43,71.12 270 top
E37  74123N  [DIL16]  11.43,97.79 270 top
F0  J15MM  [15]  81.28,40.64 270 top
F1  J15MM  [15]  78.74,40.64 90 top
F2  J15MM  [15]  76.2,40.64 90 top
I0  J15MM  [15]  210.82,73.66 270 top
I1  J15MM  [15]  208.28,73.66 270 top
I2  J15MM  [15]  205.74,73.66 270 top
I3  J15MM  [15]  203.2,73.66 270 top
I4  J15MM  [15]  198.12,73.66 270 top
I5  J15MM  [15]  200.66,73.66 270 top
I6  J15MM  [15]  195.58,73.66 270 top
I7  J15MM  [15]  193.04,73.66 270 top
I8  J15MM  [15]  81.28,73.66 270 top
I9  J15MM  [15]  83.82,73.66 270 top
I10  J15MM  [15]  78.74,73.66 270 top
I11  J15MM  [15]  76.2,73.66 270 top
R1  6.8K  [0207/10]  77.47,40.64 270 top
R2  6.8K  [0207/10]  80.01,40.64 270 top
R3  6.8K  [0207/10]  82.55,40.64 90 top
R4  6.8K  [0207/10]  199.39,40.64 90 top
R5  6.8K  [0207/10]  201.93,40.64 90 top
R6  6.8K  [0207/10]  204.47,40.64 90 top
R7  6.8K  [0207/10]  207.01,40.64 90 top
R8  6.8K  [0207/10]  209.55,73.66 270 top
R9  6.8K  [0207/10]  212.09,73.66 270 top
R10  6.8K  [0207/10]  207.01,73.66 270 top
R11  6.8K  [0207/10]  204.47,73.66 270 top
R12  6.8K  [0207/10]  189.23,40.64 90 top
R13  6.8K  [0207/10]  191.77,40.64 90 top
R14  6.8K  [0207/10]  194.31,40.64 90 top
R15  6.8K  [0207/10]  196.85,40.64 90 top
R16  6.8K  [0207/10]  194.31,73.66 270 top
R17  6.8K  [0207/10]  196.85,73.66 270 top
R18  6.8K  [0207/10]  199.39,73.66 270 top
R19  6.8K  [0207/10]  201.93,73.66 270 top
R20  6.8K  [0207/10]  85.09,40.64 90 top
R21  6.8K  [0207/10]  87.63,40.64 90 top
R22  6.8K  [0207/10]  90.17,40.64 90 top
R23  6.8K  [0207/10]  92.71,40.64 90 top
R24  6.8K  [0207/10]  77.47,73.66 270 top
R25  6.8K  [0207/10]  80.01,73.66 270 top
R26  6.8K  [0207/10]  82.55,73.66 270 top
R27  6.8K  [0207/10]  85.09,73.66 270 top
R28  470  [0207/10]  111.76,182.88 90 top
R29  27  [0207/10]  109.22,182.88 90 top
R30  12  [0207/10]  114.3,182.88 270 top
R31  10K  [0207/10]  142.24,114.3 270 top
R32  1K  [0207/10]  50.8,68.58 270 top
R33  3K  [0207/10]  53.34,68.58 90 top
R34  22K  [0207/10]  124.46,114.3 270 top
R35  15K  [0207/10]  55.88,68.58 90 top
R36  20K  [0207/10]  22.86,101.6 270 top
R37  10K  [0207/10]  20.32,101.6 270 top
R38  100  [0207/10]  124.46,129.54 90 top
R39  470  [0207/10]  238.76,76.2 270 top
R40  5.6K  [0207/10]  149.86,198.12 90 top
R41  5.6K  [0207/10]  149.86,182.88 90 top
R42  5.6K  [0207/10]  149.86,167.64 90 top
R43  5.6K  [0207/10]  149.86,152.4 90 top
R44  5.6K  [0207/10]  149.86,137.16 90 top
R45  5.6K  [0207/10]  154.94,137.16 270 top
R46  5.6K  [0207/10]  147.32,198.12 90 top
R47  5.6K  [0207/10]  147.32,182.88 90 top
R48  5.6K  [0207/10]  147.32,167.64 90 top
R49  5.6K  [0207/10]  147.32,152.4 90 top
R50  5.6K  [0207/10]  147.32,137.16 90 top
R51  5.6K  [0207/10]  152.4,137.16 270 top
R52  470  [0207/10]  111.76,144.78 90 top
R53  470  [0207/10]  177.8,104.14 90 top
S0  J15MM  [15]  200.66,40.64 270 top
S1  J15MM  [15]  198.12,40.64 270 top
S2  J15MM  [15]  203.2,40.64 270 top
S3  J15MM  [15]  205.74,40.64 270 top
S4  J15MM  [15]  193.04,40.64 270 top
S5  J15MM  [15]  195.58,40.64 270 top
S6  J15MM  [15]  190.5,40.64 270 top
S7  J15MM  [15]  187.96,40.64 270 top
S8  J15MM  [15]  88.9,40.64 270 top
S9  J15MM  [15]  91.44,40.64 270 top
S10  J15MM  [15]  86.36,40.64 270 top
S11  J15MM  [15]  83.82,40.64 270 top
T1  [TO92]  110.49,195.58 180 top
T2  [TO92]  146.05,124.46 0 top
U$1  OUTLINE-OMNIBUS  [OMNIBUS]  0,0 0 top
U$2  [EDGE-CON8]  0,0 0 top

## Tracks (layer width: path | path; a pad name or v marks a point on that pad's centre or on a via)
+3V3  (via drill 0.61)
  Top 0.635: I11.1 I10.1 I8.1 I9.1 | E30.10 47.62,70.49 47.62,71.76 E30.12 40.01,73.66 | E37.3 6.99,102.24 6.99,103.51 E37.2 | 40.01,73.66 40.01,74.3 E30.2 36.2,78.11 36.2,78.74 24.77,90.17 24.77,100.33 v20.32,100.33 | 40.01,73.66 40.01,73.03 E30.4 | I7.1 I6.1 I4.1 I5.1 I3.1 I2.1 I1.1 I0.1 | v174.62,69.85 174.62,74.3 | 174.62,74.3 E12.13 | 174.62,74.3 v174.62,80.01 | D386.C R52.2 111.76,149.23 114.3,146.69 C6.1 114.3,145.42 123.19,136.53 123.19,127.64 127.64,123.19 127.64,115.57 | 131.44,84.46 131.44,104.78 130.81,105.41 128.27,105.41 127.64,106.05 127.64,107.32 | 131.44,84.46 131.44,79.38 E18.2 | 127.64,107.32 E19.3 | 127.64,115.57 130.81,115.57 135.25,111.13 135.25,103.51 E19.11 | 127.64,115.57 127.64,107.32 | v138.43,76.2 v138.43,68.58 | 131.44,84.46 v128.27,81.28
  Bottom 0.635: v20.32,100.33 10.16,100.33 8.89,101.6 E37.3 | I11.1 38.1,81.28 36.2,79.38 36.2,76.84 37.47,76.84 E30.2 | 162.56,69.85 148.59,69.85 147.32,68.58 E18.10 v138.43,68.58 | 162.56,69.85 163.83,71.12 E12.4 | 162.56,69.85 v174.62,69.85 | v174.62,80.01 191.13,80.01 192.41,81.28 I7.1 | E23.2 110.49,109.22 111.76,110.49 127,110.49 128.27,109.22 E19.3 | E18.2 v138.43,76.2 | v128.27,81.28 I9.1
-15V  (via drill 0.61)
  Top 0.635: R9.1 R8.1 R10.1 R11.1 R19.1 R18.1 R17.1 R16.1 186.69,78.74 v186.69,81.28 | R24.1 R25.1 R26.1 | 54.61,31.75 54.61,24.13 55.24,23.5 v55.24,15.24 | 54.61,31.75 54.61,36.83 C9.- | v73.66,78.74 72.39,77.47 72.39,34.29 69.85,31.75 54.61,31.75 | v93.34,86.36 85.72,78.74 R27.1
  Bottom 0.635: R27.1 R26.1 | v55.24,15.24 55.24,13.97 U$2.DB2 | R24.1 v73.66,78.74 | v186.69,81.28 181.61,86.36 v93.34,86.36
ACTIVE\  (via drill 0.61)
  Top 0.254: v146.05,69.85 147.96,71.76 147.96,74.3 E15.2 v152.4,73.66
  Bottom 0.254: v146.05,69.85 137.16,69.85 135.89,68.58 E18.5 | v152.4,73.66 E15.12
C01
  Top 0.254: 7.62,192.41 8.26,192.41 D1.C | 7.62,192.41 6.99,192.41 D7.C | 7.62,192.41 7.62,180.34 6.35,179.07 D8.C 6.99,177.17 8.26,177.17 D2.C 8.89,176.53 10.16,175.26 10.16,165.1 8.89,163.83 D3.C | D11.C 6.99,131.45 8.26,131.45 D5.C | 7.62,146.69 8.26,146.69 D4.C | 7.62,146.69 6.99,146.69 D10.C 6.35,148.59 5.08,149.86 5.08,160.02 6.35,161.29 D9.C | 7.62,146.69 7.62,134.62 6.35,133.35 D11.C | D12.C 6.35,118.11 5.08,119.38 5.08,129.54 6.35,130.81 D11.C
  Bottom 0.254: D6.C 8.26,116.21 6.99,116.21 D12.C 6.35,112.4 13.34,105.41 16.51,105.41 E34.6 | D9.C 6.99,161.93 8.26,161.93 D3.C
C02
  Top 0.254: E34.4 21.59,105.41 21.59,109.22 15.24,115.57 D18.C 14.61,116.21 13.34,116.21 D24.C 12.7,118.11 13.97,119.38 13.97,131.45 | 13.97,131.45 14.61,131.45 D17.C | 13.97,131.45 13.34,131.45 D23.C 12.7,133.35 13.97,134.62 13.97,146.69 | 13.97,146.69 14.61,146.69 D16.C | 13.97,146.69 13.34,146.69 D22.C 12.7,148.59 13.97,149.86 13.97,161.93 | D13.C 14.61,192.41 13.34,192.41 D19.C 12.7,191.77 13.97,190.5 13.97,177.17 | 13.97,161.93 14.61,161.93 D15.C | 13.97,161.93 13.34,161.93 D21.C 12.7,163.83 13.97,165.1 13.97,177.17 | 13.97,177.17 14.61,177.17 D14.C | 13.97,177.17 13.34,177.17 D20.C
C03
  Top 0.254: E34.2 21.59,110.49 D30.C 20.95,116.21 19.68,116.21 D36.C 19.05,118.11 20.32,119.38 20.32,131.45 | 20.32,131.45 20.95,131.45 D29.C | 20.32,131.45 19.68,131.45 D35.C 19.05,133.35 20.32,134.62 20.32,146.69 | 20.32,146.69 20.95,146.69 D28.C | 20.32,146.69 19.68,146.69 D34.C 19.05,148.59 20.32,149.86 20.32,161.93 | D25.C 20.95,192.41 19.68,192.41 D31.C 19.05,191.77 20.32,190.5 20.32,177.17 | 20.32,161.93 20.95,161.93 D27.C | 20.32,161.93 19.68,161.93 D33.C 19.05,163.83 20.32,165.1 20.32,177.17 | 20.32,177.17 20.95,177.17 D26.C | 20.32,177.17 19.68,177.17 D32.C
C04
  Top 0.254: D48.C 26.04,116.21 27.3,116.21 D42.C 27.94,118.75 29.21,118.75 | 29.21,118.75 32.38,118.75 33.02,118.11 33.02,104.14 E34.12 | 29.21,118.75 29.21,129.54 27.94,130.81 D41.C 27.3,131.45 26.04,131.45 D47.C 25.4,133.35 26.67,134.62 26.67,146.69 | 26.67,146.69 27.3,146.69 D40.C | 26.67,146.69 26.04,146.69 D46.C 25.4,148.59 26.67,149.86 26.67,161.93 | 26.67,161.93 27.3,161.93 D39.C | 26.67,161.93 26.04,161.93 D45.C 25.4,163.83 26.67,165.1 26.67,177.17 | 26.67,177.17 27.3,177.17 D38.C | 26.67,177.17 26.04,177.17 D44.C 25.4,179.07 26.67,180.34 26.67,192.41 | 26.67,192.41 27.3,192.41 D37.C | 26.67,192.41 26.04,192.41 D43.C
C05
  Top 0.254: E34.10 31.75,100.33 D60.C | 33.02,131.45 33.66,131.45 D53.C | 33.02,131.45 32.38,131.45 D59.C 31.75,133.35 33.02,134.62 33.02,146.69 | 33.02,146.69 33.66,146.69 D52.C | 33.02,146.69 32.38,146.69 D58.C 31.75,148.59 33.02,149.86 33.02,161.93 | D49.C 33.66,192.41 32.38,192.41 D55.C 31.75,191.77 33.02,190.5 33.02,177.17 | 33.02,161.93 33.66,161.93 D51.C | 33.02,161.93 32.38,161.93 D57.C 31.75,163.83 33.02,165.1 33.02,177.17 | 33.02,177.17 33.66,177.17 D50.C | 33.02,177.17 32.38,177.17 D56.C | 33.02,131.45 33.02,119.38 34.29,118.11 D54.C
  Bottom 0.254: D60.C 32.38,116.21 33.66,116.21 D54.C
C06
  Top 0.254: E34.8 38.1,93.98 D72.C 38.73,116.21 40.01,116.21 D66.C 40.64,118.11 39.37,119.38 39.37,131.45 | 39.37,131.45 40.01,131.45 D65.C | 39.37,131.45 38.73,131.45 D71.C 38.1,133.35 39.37,134.62 39.37,146.69 | 39.37,146.69 40.01,146.69 D64.C | 39.37,146.69 38.73,146.69 D70.C 38.1,148.59 39.37,149.86 39.37,161.93 | D61.C 40.01,192.41 38.73,192.41 D67.C 38.1,191.77 39.37,190.5 39.37,177.17 | 39.37,161.93 40.01,161.93 D63.C | 39.37,161.93 38.73,161.93 D69.C 38.1,163.83 39.37,165.1 39.37,177.17 | 39.37,177.17 40.01,177.17 D62.C | 39.37,177.17 38.73,177.17 D68.C
C07
  Top 0.254: E28.6 50.16,99.7 50.16,112.4 46.99,115.57 D78.C 46.35,116.21 45.09,116.21 D84.C 44.45,118.11 45.72,119.38 45.72,131.45 | 45.72,131.45 46.35,131.45 D77.C | 45.72,131.45 45.09,131.45 D83.C 44.45,133.35 45.72,134.62 45.72,146.69 | 45.72,146.69 46.35,146.69 D76.C | 45.72,146.69 45.09,146.69 D82.C 44.45,148.59 45.72,149.86 45.72,161.93 | D73.C 46.35,192.41 45.09,192.41 D79.C 44.45,191.77 45.72,190.5 45.72,177.17 | 45.72,161.93 46.35,161.93 D75.C | 45.72,161.93 45.09,161.93 D81.C 44.45,163.83 45.72,165.1 45.72,177.17 | 45.72,177.17 46.35,177.17 D74.C | 45.72,177.17 45.09,177.17 D80.C
C08
  Top 0.254: E28.4 53.34,101.6 D90.C 52.7,116.21 51.44,116.21 D96.C 50.8,118.11 52.07,119.38 52.07,131.45 | 52.07,131.45 52.7,131.45 D89.C | 52.07,131.45 51.44,131.45 D95.C 50.8,133.35 52.07,134.62 52.07,146.69 | 52.07,146.69 52.7,146.69 D88.C | 52.07,146.69 51.44,146.69 D94.C 50.8,148.59 52.07,149.86 52.07,161.93 | D85.C 52.7,192.41 51.44,192.41 D91.C 50.8,191.77 52.07,190.5 52.07,177.17 | 52.07,161.93 52.7,161.93 D87.C | 52.07,161.93 51.44,161.93 D93.C 50.8,163.83 52.07,165.1 52.07,177.17 | 52.07,177.17 52.7,177.17 D86.C | 52.07,177.17 51.44,177.17 D92.C
C09
  Top 0.254: D97.C 59.05,192.41 57.78,192.41 D103.C 57.15,191.77 58.42,190.5 58.42,177.17 | D105.C 57.78,161.93 59.05,161.93 D99.C | 58.42,177.17 59.05,177.17 D98.C | 58.42,177.17 57.78,177.17 D104.C | 58.42,177.17 58.42,165.1 57.15,163.83 D105.C | E28.2 59.69,107.95 D102.C 59.05,116.21 57.78,116.21 D108.C 57.15,118.11 58.42,119.38 58.42,131.45 | 58.42,131.45 59.05,131.45 D101.C | 58.42,131.45 57.78,131.45 D107.C 57.15,133.35 58.42,134.62 58.42,146.69 | 58.42,146.69 59.05,146.69 D100.C | 58.42,146.69 57.78,146.69 D106.C | 58.42,146.69 58.42,160.02 57.15,161.29 D105.C
C10
  Top 0.254: D109.C 65.41,192.41 64.14,192.41 D115.C 63.5,191.77 64.77,190.5 64.77,177.17 | D117.C 64.14,161.93 65.41,161.93 D111.C | 64.77,177.17 65.41,177.17 D110.C | 64.77,177.17 64.14,177.17 D116.C | 64.77,177.17 64.77,165.1 63.5,163.83 D117.C | E28.12 66.04,104.14 D114.C 65.41,116.21 64.14,116.21 D120.C 63.5,118.11 64.77,119.38 64.77,131.45 | 64.77,131.45 65.41,131.45 D113.C | 64.77,131.45 64.14,131.45 D119.C 63.5,133.35 64.77,134.62 64.77,146.69 | 64.77,146.69 65.41,146.69 D112.C | 64.77,146.69 64.14,146.69 D118.C | 64.77,146.69 64.77,160.02 63.5,161.29 D117.C
C11
  Top 0.254: E28.10 69.22,102.24 69.22,116.21 D132.C 70.48,116.21 71.75,116.21 D126.C 72.39,118.11 71.12,119.38 71.12,131.45 | 71.12,131.45 71.75,131.45 D125.C | 71.12,131.45 70.48,131.45 D131.C 69.85,133.35 71.12,134.62 71.12,146.69 | 71.12,146.69 71.75,146.69 D124.C | 71.12,146.69 70.48,146.69 D130.C 69.85,148.59 71.12,149.86 71.12,161.93 | D121.C 71.75,192.41 70.48,192.41 D127.C 69.85,191.77 71.12,190.5 71.12,177.17 | 71.12,161.93 71.75,161.93 D123.C | 71.12,161.93 70.48,161.93 D129.C 69.85,163.83 71.12,165.1 71.12,177.17 | 71.12,177.17 71.75,177.17 D122.C | 71.12,177.17 70.48,177.17 D128.C
C12
  Top 0.254: D142.C 76.83,146.69 78.11,146.69 D136.C | 77.47,161.93 78.11,161.93 D135.C | 77.47,161.93 76.83,161.93 D141.C 76.2,163.83 77.47,165.1 77.47,177.17 | 77.47,161.93 77.47,149.86 76.2,148.59 D142.C | 77.47,177.17 78.11,177.17 D134.C | 77.47,177.17 76.83,177.17 D140.C 76.2,179.07 77.47,180.34 77.47,192.41 | 77.47,192.41 78.11,192.41 D133.C | 77.47,192.41 76.83,192.41 D139.C | D138.C 78.11,116.21 76.83,116.21 D144.C 76.2,118.75 73.66,121.29 | 73.66,121.29 73.66,128.27 76.2,130.81 D143.C 76.83,131.45 77.47,131.45 | 73.66,121.29 73.66,118.75 74.3,118.11 74.3,87 69.22,87 64.77,91.44 E28.8 | 77.47,131.45 78.11,131.45 D137.C | 77.47,131.45 77.47,144.78 76.2,146.05 D142.C
C13
  Top 0.254: D145.C 84.45,192.41 83.19,192.41 D151.C 82.55,191.77 83.82,190.5 83.82,177.17 | D153.C 83.19,161.93 84.45,161.93 D147.C | 83.82,177.17 84.45,177.17 D146.C | 83.82,177.17 83.19,177.17 D152.C | 83.82,177.17 83.82,165.1 82.55,163.83 D153.C | 84.45,116.21 83.19,116.21 D156.C 82.55,118.11 83.82,119.38 83.82,131.45 | 84.45,116.21 84.45,106.05 E24.2 | 84.45,116.21 D150.C | 83.82,131.45 84.45,131.45 D149.C | 83.82,131.45 83.19,131.45 D155.C 82.55,133.35 83.82,134.62 83.82,146.69 | 83.82,146.69 84.45,146.69 D148.C | 83.82,146.69 83.19,146.69 D154.C | 83.82,146.69 83.82,160.02 82.55,161.29 D153.C
C14  (via drill 0.61)
  Top 0.254: 90.17,116.21 90.81,116.21 D162.C | 90.17,116.21 89.53,116.21 D168.C 88.9,118.11 90.17,119.38 90.17,131.45 | 90.17,116.21 v90.17,101.6 | 90.17,131.45 90.81,131.45 D161.C | 90.17,131.45 89.53,131.45 D167.C 88.9,133.35 90.17,134.62 90.17,146.69 | 90.17,146.69 90.81,146.69 D160.C | 90.17,146.69 89.53,146.69 D166.C 88.9,148.59 90.17,149.86 90.17,161.93 | D157.C 90.81,192.41 89.53,192.41 D163.C 88.9,191.77 90.17,190.5 90.17,177.17 | 90.17,161.93 90.81,161.93 D159.C | 90.17,161.93 89.53,161.93 D165.C 88.9,163.83 90.17,165.1 90.17,177.17 | 90.17,177.17 90.81,177.17 D158.C | 90.17,177.17 89.53,177.17 D164.C
  Bottom 0.254: v90.17,101.6 E24.12
C15
  Top 0.254: 95.89,116.21 95.89,98.43 E24.10 | 95.89,116.21 97.16,116.21 D174.C 97.79,118.11 96.52,119.38 96.52,131.45 | 95.89,116.21 D180.C | 96.52,131.45 97.16,131.45 D173.C | 96.52,131.45 95.89,131.45 D179.C 95.25,133.35 96.52,134.62 96.52,146.69 | 96.52,146.69 97.16,146.69 D172.C | 96.52,146.69 95.89,146.69 D178.C 95.25,148.59 96.52,149.86 96.52,161.93 | D169.C 97.16,192.41 95.89,192.41 D175.C 95.25,191.77 96.52,190.5 96.52,177.17 | 96.52,161.93 97.16,161.93 D171.C | 96.52,161.93 95.89,161.93 D177.C 95.25,163.83 96.52,165.1 96.52,177.17 | 96.52,177.17 97.16,177.17 D170.C | 96.52,177.17 95.89,177.17 D176.C
C16
  Top 0.254: E24.8 100.33,97.79 100.33,114.3 101.6,115.57 D192.C | 102.87,146.69 103.5,146.69 D184.C | 102.87,146.69 102.23,146.69 D190.C 101.6,148.59 102.87,149.86 102.87,161.93 | 102.87,146.69 102.87,134.62 101.6,133.35 D191.C 102.23,131.45 103.5,131.45 D185.C 104.14,130.81 105.41,129.54 105.41,119.38 104.14,118.11 D186.C | D181.C 103.5,192.41 102.23,192.41 D187.C 101.6,191.77 102.87,190.5 102.87,177.17 | 102.87,161.93 103.5,161.93 D183.C | 102.87,161.93 102.23,161.93 D189.C 101.6,163.83 102.87,165.1 102.87,177.17 | 102.87,177.17 103.5,177.17 D182.C | 102.87,177.17 102.23,177.17 D188.C
  Bottom 0.254: D186.C 103.5,116.21 102.23,116.21 D192.C
C17
  Top 0.254: D200.C 163.19,177.17 164.47,177.17 D194.C | 163.83,192.41 164.47,192.41 D193.C | 163.83,192.41 163.19,192.41 D199.C | 163.83,192.41 163.83,180.34 162.56,179.07 D200.C | 163.83,161.93 164.47,161.93 D195.C | 163.83,161.93 163.19,161.93 D201.C 162.56,163.83 161.29,165.1 161.29,175.26 162.56,176.53 D200.C | 163.83,161.93 163.83,149.86 162.56,148.59 D202.C 163.19,146.69 164.47,146.69 D196.C 165.1,146.05 166.37,144.78 166.37,129.54 | D203.C 163.19,131.45 164.47,131.45 D197.C 165.1,130.81 166.37,129.54 | D204.C 163.19,116.21 164.47,116.21 D198.C 165.1,118.75 166.37,118.75 | 166.37,118.75 169.54,118.75 170.18,118.11 170.18,115.57 174.62,111.13 174.62,104.14 E10.2 | 166.37,118.75 166.37,129.54
C18  (via drill 0.61)
  Top 0.254: v170.18,102.87 168.91,104.14 D216.C | 170.18,131.45 170.81,131.45 D209.C | 170.18,131.45 169.54,131.45 D215.C 168.91,133.35 170.18,134.62 170.18,146.69 | 170.18,146.69 170.81,146.69 D208.C | 170.18,146.69 169.54,146.69 D214.C 168.91,148.59 170.18,149.86 170.18,161.93 | D211.C 169.54,192.41 170.81,192.41 D205.C 171.45,191.77 172.72,190.5 172.72,180.34 171.45,179.07 D206.C 170.81,177.17 170.18,177.17 | 170.18,161.93 170.81,161.93 D207.C | 170.18,161.93 169.54,161.93 D213.C 168.91,163.83 170.18,165.1 170.18,177.17 | 170.18,177.17 169.54,177.17 D212.C | 170.18,131.45 170.18,119.38 171.45,118.11 D210.C
  Bottom 0.254: D216.C 169.54,116.21 170.81,116.21 D210.C | v170.18,102.87 187.96,102.87 189.23,101.6 E10.12
C19  (via drill 0.61)
  Top 0.254: D222.C 177.16,116.21 175.9,116.21 D228.C 175.26,118.11 176.53,119.38 176.53,131.45 | v186.69,111.76 186.69,100.33 E10.10 | 176.53,131.45 177.16,131.45 D221.C | 176.53,131.45 175.9,131.45 D227.C 175.26,133.35 176.53,134.62 176.53,146.69 | 176.53,146.69 177.16,146.69 D220.C | 176.53,146.69 175.9,146.69 D226.C 175.26,148.59 176.53,149.86 176.53,161.93 | D217.C 177.16,192.41 175.9,192.41 D223.C 175.26,191.77 176.53,190.5 176.53,177.17 | 176.53,161.93 177.16,161.93 D219.C | 176.53,161.93 175.9,161.93 D225.C 175.26,163.83 176.53,165.1 176.53,177.17 | 176.53,177.17 177.16,177.17 D218.C | 176.53,177.17 175.9,177.17 D224.C
  Bottom 0.254: v186.69,111.76 183.51,114.94 179.71,114.94 D222.C
C20
  Top 0.254: D240.C 182.25,116.21 183.51,116.21 D234.C | E10.8 186.06,95.89 186.06,107.95 181.61,112.4 D240.C | 182.88,131.45 183.51,131.45 D233.C | 182.88,131.45 182.25,131.45 D239.C 181.61,133.35 182.88,134.62 182.88,146.69 | 182.88,146.69 183.51,146.69 D232.C | 182.88,146.69 182.25,146.69 D238.C 181.61,148.59 182.88,149.86 182.88,161.93 | D229.C 183.51,192.41 182.25,192.41 D235.C 181.61,191.77 182.88,190.5 182.88,177.17 | 182.88,161.93 183.51,161.93 D231.C | 182.88,161.93 182.25,161.93 D237.C 181.61,163.83 182.88,165.1 182.88,177.17 | 182.88,177.17 183.51,177.17 D230.C | 182.88,177.17 182.25,177.17 D236.C | 182.88,131.45 182.88,119.38 181.61,118.11 D240.C
C21
  Top 0.254: E8.6 207.01,100.33 200.03,100.33 200.03,107.32 D246.C 189.87,116.21 188.59,116.21 D252.C 187.96,118.11 189.23,119.38 189.23,131.45 | 189.23,131.45 189.87,131.45 D245.C | 189.23,131.45 188.59,131.45 D251.C 187.96,133.35 189.23,134.62 189.23,146.69 | 189.23,146.69 189.87,146.69 D244.C | 189.23,146.69 188.59,146.69 D250.C 187.96,148.59 189.23,149.86 189.23,161.93 | D241.C 189.87,192.41 188.59,192.41 D247.C 187.96,191.77 189.23,190.5 189.23,177.17 | 189.23,161.93 189.87,161.93 D243.C | 189.23,161.93 188.59,161.93 D249.C 187.96,163.83 189.23,165.1 189.23,177.17 | 189.23,177.17 189.87,177.17 D242.C | 189.23,177.17 188.59,177.17 D248.C
C22  (via drill 0.61)
  Top 0.254: D258.C 196.22,116.21 194.94,116.21 D264.C 194.31,118.11 195.58,119.38 195.58,131.45 | v211.46,114.3 211.46,100.97 E8.4 | 195.58,131.45 196.22,131.45 D257.C | 195.58,131.45 194.94,131.45 D263.C 194.31,133.35 195.58,134.62 195.58,146.69 | 195.58,146.69 196.22,146.69 D256.C | 195.58,146.69 194.94,146.69 D262.C 194.31,148.59 195.58,149.86 195.58,161.93 | D253.C 196.22,192.41 194.94,192.41 D259.C 194.31,191.77 195.58,190.5 195.58,177.17 | 195.58,161.93 196.22,161.93 D255.C | 195.58,161.93 194.94,161.93 D261.C 194.31,163.83 195.58,165.1 195.58,177.17 | 195.58,177.17 196.22,177.17 D254.C | 195.58,177.17 194.94,177.17 D260.C
  Bottom 0.254: v211.46,114.3 210.82,114.94 198.75,114.94 D258.C
C23  (via drill 0.61)
  Top 0.254: v207.65,102.87 203.2,102.87 D270.C 202.56,116.21 201.29,116.21 D276.C 200.66,118.11 201.93,119.38 201.93,131.45 | 201.93,131.45 202.56,131.45 D269.C | 201.93,131.45 201.29,131.45 D275.C 200.66,133.35 201.93,134.62 201.93,146.69 | 201.93,146.69 202.56,146.69 D268.C | 201.93,146.69 201.29,146.69 D274.C 200.66,148.59 201.93,149.86 201.93,161.93 | D265.C 202.56,192.41 201.29,192.41 D271.C 200.66,191.77 201.93,190.5 201.93,177.17 | 201.93,161.93 202.56,161.93 D267.C | 201.93,161.93 201.29,161.93 D273.C 200.66,163.83 201.93,165.1 201.93,177.17 | 201.93,177.17 202.56,177.17 D266.C | 201.93,177.17 201.29,177.17 D272.C
  Bottom 0.254: v207.65,102.87 210.82,102.87 212.09,104.14 E8.2
C24
  Top 0.254: E8.12 219.71,101.6 215.9,97.79 210.82,97.79 210.82,113.67 209.55,114.94 D282.C 208.91,116.21 207.65,116.21 D288.C 207.01,118.11 208.28,119.38 208.28,131.45 | 208.28,131.45 208.91,131.45 D281.C | 208.28,131.45 207.65,131.45 D287.C 207.01,133.35 208.28,134.62 208.28,146.69 | 208.28,146.69 208.91,146.69 D280.C | 208.28,146.69 207.65,146.69 D286.C 207.01,148.59 208.28,149.86 208.28,161.93 | D277.C 208.91,192.41 207.65,192.41 D283.C 207.01,191.77 208.28,190.5 208.28,177.17 | 208.28,161.93 208.91,161.93 D279.C | 208.28,161.93 207.65,161.93 D285.C 207.01,163.83 208.28,165.1 208.28,177.17 | 208.28,177.17 208.91,177.17 D278.C | 208.28,177.17 207.65,177.17 D284.C
C25  (via drill 0.61)
  Top 0.254: v215.9,101.6 D294.C 215.26,116.21 214,116.21 D300.C 213.36,118.11 214.63,119.38 214.63,131.45 | 214.63,131.45 215.26,131.45 D293.C | 214.63,131.45 214,131.45 D299.C 213.36,133.35 214.63,134.62 214.63,146.69 | 214.63,146.69 215.26,146.69 D292.C | 214.63,146.69 214,146.69 D298.C 213.36,148.59 214.63,149.86 214.63,161.93 | D289.C 215.26,192.41 214,192.41 D295.C 213.36,191.77 214.63,190.5 214.63,177.17 | 214.63,161.93 215.26,161.93 D291.C | 214.63,161.93 214,161.93 D297.C 213.36,163.83 214.63,165.1 214.63,177.17 | 214.63,177.17 215.26,177.17 D290.C | 214.63,177.17 214,177.17 D296.C
  Bottom 0.254: E8.10 v215.9,101.6
C26
  Top 0.254: E8.8 222.88,93.35 222.88,116.21 D306.C 221.62,116.21 220.34,116.21 D312.C 219.71,118.11 220.98,119.38 220.98,131.45 | 220.98,131.45 221.62,131.45 D305.C | 220.98,131.45 220.34,131.45 D311.C 219.71,133.35 220.98,134.62 220.98,146.69 | 220.98,146.69 221.62,146.69 D304.C | 220.98,146.69 220.34,146.69 D310.C 219.71,148.59 220.98,149.86 220.98,161.93 | D301.C 221.62,192.41 220.34,192.41 D307.C 219.71,191.77 220.98,190.5 220.98,177.17 | 220.98,161.93 221.62,161.93 D303.C | 220.98,161.93 220.34,161.93 D309.C 219.71,163.83 220.98,165.1 220.98,177.17 | 220.98,177.17 221.62,177.17 D302.C | 220.98,177.17 220.34,177.17 D308.C
C27  (via drill 0.61)
  Top 0.254: v234.31,95.25 231.14,98.43 231.14,113.03 228.6,115.57 D318.C 227.97,116.21 226.69,116.21 D324.C 226.06,118.11 227.33,119.38 227.33,131.45 | 227.33,131.45 227.97,131.45 D317.C | 227.33,131.45 226.69,131.45 D323.C 226.06,133.35 227.33,134.62 227.33,146.69 | 227.33,146.69 227.97,146.69 D316.C | 227.33,146.69 226.69,146.69 D322.C 226.06,148.59 227.33,149.86 227.33,161.93 | D313.C 227.97,192.41 226.69,192.41 D319.C 226.06,191.77 227.33,190.5 227.33,177.17 | 227.33,161.93 227.97,161.93 D315.C | 227.33,161.93 226.69,161.93 D321.C 226.06,163.83 227.33,165.1 227.33,177.17 | 227.33,177.17 227.97,177.17 D314.C | 227.33,177.17 226.69,177.17 D320.C
  Bottom 0.254: v234.31,95.25 241.3,95.25 242.57,93.98 E3.6
C28  (via drill 0.61)
  Top 0.254: D336.C 233.04,116.21 234.31,116.21 D330.C | v234.31,100.33 232.41,102.24 D336.C | 233.68,131.45 234.31,131.45 D329.C | 233.68,131.45 233.04,131.45 D335.C 232.41,133.35 233.68,134.62 233.68,146.69 | 233.68,146.69 234.31,146.69 D328.C | 233.68,146.69 233.04,146.69 D334.C 232.41,148.59 233.68,149.86 233.68,161.93 | D325.C 234.31,192.41 233.04,192.41 D331.C 232.41,191.77 233.68,190.5 233.68,177.17 | 233.68,161.93 234.31,161.93 D327.C | 233.68,161.93 233.04,161.93 D333.C 232.41,163.83 233.68,165.1 233.68,177.17 | 233.68,177.17 234.31,177.17 D326.C | 233.68,177.17 233.04,177.17 D332.C | 233.68,131.45 233.68,119.38 232.41,118.11 D336.C
  Bottom 0.254: v234.31,100.33 237.49,100.33 238.12,99.7 241.94,99.7 242.57,99.06 E3.4
C29
  Top 0.254: D337.C 240.66,192.41 239.4,192.41 D343.C 238.76,191.77 240.03,190.5 240.03,177.17 | D345.C 239.4,161.93 240.66,161.93 D339.C | 240.03,177.17 240.66,177.17 D338.C | 240.03,177.17 239.4,177.17 D344.C | 240.03,177.17 240.03,165.1 238.76,163.83 D345.C | E3.2 241.3,106.68 D342.C 240.66,116.21 239.4,116.21 D348.C 238.76,118.11 240.03,119.38 240.03,131.45 | 240.03,131.45 240.66,131.45 D341.C | 240.03,131.45 239.4,131.45 D347.C 238.76,133.35 240.03,134.62 240.03,146.69 | 240.03,146.69 240.66,146.69 D340.C | 240.03,146.69 239.4,146.69 D346.C | 240.03,146.69 240.03,160.02 238.76,161.29 D345.C
C30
